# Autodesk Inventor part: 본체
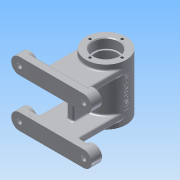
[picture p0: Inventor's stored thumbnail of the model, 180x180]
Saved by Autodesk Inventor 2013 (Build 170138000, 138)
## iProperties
Created: 2015-11
Part Number: 본체
Material: 알루미늄 6061
Document SubType Name: Modeling
Designer: Administrator
Density: 2.71 g/cm^3
Mass: 359.017 g
Surface Area: 459.644 cm^2
Volume: 132.479 cm^3
Author: Administrator
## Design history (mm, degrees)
sketch "스케치1"
  geometry: L1 (-40, 40)-(40, 40); L2 (40, 20)-(-40, 20); L3 (-40, -40)-(40, -40); L4 (40, -20)-(-40, -20); A1 r 10 centre (-40, 30) between (-40, 40) and (-40, 20); A2 r 10 centre (40, 30) between (40, 20) and (40, 40); A3 r 10 centre (-40, -30) between (-40, -20) and (-40, -40); A4 r 10 centre (40, -30) between (40, -40) and (40, -20); 1 further point
  constraints: 8 end point, 8 point on circle, 4 centre point, 3 tangent, 1 parallel
extrude "돌출1" new body sketch "스케치1" distance "d6" = 10; taper "d7" = 0 deg
sketch "스케치2"
  geometry: C1 r 10 at (-40, 30); C2 r 10 at (40, 30); A1 r 10 centre (-40, 30) between (-40, 40) and (-40, 20) reference; A2 r 10 centre (40, 30) between (40, 20) and (40, 40) reference; 1 further point
  constraints: 2 centre point, 2 coincident
  dimensions: "d8" = 20 diameter of C1; "d9" = 20 diameter of C2
extrude "돌출2" join sketch "스케치2" distance "d10" = 3; taper "d11" = 0 deg
sketch "스케치3"
  geometry: C1 r 10 at (-40, -30); C2 r 10 at (40, -30); A1 r 10 centre (40, -30) between (40, -40) and (40, -20) reference; A2 r 10 centre (-40, -30) between (-40, -20) and (-40, -40) reference; 1 further point
  constraints: 2 centre point, 2 coincident
  dimensions: "d12" = 20 diameter of C1; "d13" = 20 diameter of C2
extrude "돌출3" join sketch "스케치3" distance "d14" = 3; taper "d15" = 0 deg
sketch "스케치4"
  geometry: L1 (0, 0)-(0, 68); C1 r 25 at (0, 68)
  constraints: 2 end point, 1 centre point, 1 coincident, 1 vertical
  dimensions: "d16" = 68 distance of L1.start L1.end; "d17" = 50 diameter of C1
extrude "돌출4" join sketch "스케치4" stored distance "d18" = 70; taper "d19" = 0 deg
sketch "스케치5"
  geometry: L1 (0, 10)-(80, 10) reference; L2 (65, 68)-(65, 10); L3 (65, 10)-(15, 10); L4 (15, 10)-(15, 68); L5 (15, 68)-(65, 68); 1 further point
  constraints: 8 end point, 3 perpendicular, 2 point on line
extrude "돌출5" join sketch "스케치5" distance "d23" = 8; taper "d24" = 0 deg
sketch "스케치6"
  geometry: L1 (0, 10)-(80, 10) reference; L2 (65, 68)-(65, 10); L3 (65, 10)-(15, 10); L4 (15, 10)-(15, 68); L5 (15, 68)-(65, 68); 1 further point
  constraints: 8 end point, 3 perpendicular, 2 point on line
extrude "돌출6" join sketch "스케치6" distance "d28" = 8; taper "d29" = 0 deg
sketch "스케치7"
  geometry: L1 (0, 0)-(33, 0); L2 (33, -20)-(23, -20); L3 (23, -20)-(23, 20); L4 (23, -20)-(53, -20); L5 (53, -20)-(53, 20); L6 (53, 20)-(23, 20)
  constraints: 12 end point, 2 perpendicular, 1 horizontal, 1 parallel
extrude "돌출7" join sketch "스케치7" stored distance "d40" = 8; taper "d41" = 0 deg
hole "구멍1" diameter "d44" = 6; stored, may be unused: countersink angle "d48" = 90 deg, drill point angle "d50" = 118 deg; dims "d42" = 10, "d43" = 10, "d45" = 6, "d46" = 12, "d47" = 4, "d49" = 13
hole "구멍2" diameter "d53" = 6; stored, may be unused: countersink angle "d57" = 90 deg, drill point angle "d59" = 118 deg; dims "d51" = 10, "d52" = 10, "d54" = 6, "d55" = 12, "d56" = 4, "d58" = 13
hole "구멍3" diameter "d62" = 6; stored, may be unused: countersink angle "d66" = 90 deg, drill point angle "d68" = 118 deg; dims "d60" = 10, "d61" = 10, "d63" = 6, "d64" = 12, "d65" = 4, "d67" = 13
hole "구멍4" diameter "d71" = 6; stored, may be unused: countersink angle "d75" = 90 deg, drill point angle "d77" = 118 deg; dims "d69" = 10, "d70" = 10, "d72" = 6, "d73" = 12, "d74" = 4, "d76" = 13
chamfer "모따기1" distance "d78" = 1; stored, may be unused: second distance "d79" = 2, angle "d80" = 45 deg
chamfer "모따기2" distance "d81" = 1; stored, may be unused: second distance "d82" = 2, angle "d83" = 45 deg
chamfer "모따기3" distance "d84" = 1; stored, may be unused: second distance "d85" = 2, angle "d86" = 45 deg
chamfer "모따기4" distance "d87" = 1; stored, may be unused: second distance "d88" = 2, angle "d89" = 45 deg
node "작업 평면2"
sketch "스케치8"
  geometry: C1 r 5 at (0, 0); 1 further point
  constraints: 1 centre point, 1 coincident
  dimensions: "d91" = 10 diameter of C1
extrude "돌출8" join sketch "스케치8" stored distance "d92" = 8; taper "d93" = 0 deg
sketch "스케치9"
  geometry: C1 r 25 at (0, 0) reference; C2 r 16 at (0, 0); 1 further point
  constraints: 1 centre point, 1 coincident
  dimensions: "d94" = 32 diameter of C2
extrude "돌출9" cut sketch "스케치9" distance "d95" = 12; taper "d96" = 0 deg
sketch "스케치10"
  geometry: C1 r 16 at (0, 0) reference; C2 r 14 at (0, 0); 1 further point
  constraints: 1 centre point, 1 coincident
  dimensions: "d97" = 28 diameter of C2
extrude "돌출10" cut sketch "스케치10" distance "d98" = 2; taper "d99" = 0 deg
sketch "스케치11"
  geometry: C1 r 25 at (0, 0) reference; C2 r 16 at (0, 0); 1 further point
  constraints: 1 centre point, 1 coincident
  dimensions: "d100" = 32 diameter of C2
extrude "돌출11" cut sketch "스케치11" distance "d101" = 12; taper "d102" = 0 deg
sketch "스케치12"
  geometry: C1 r 16 at (0, 0) reference; C2 r 14 at (0, 0); 1 further point
  constraints: 1 centre point, 1 coincident
  dimensions: "d103" = 28 diameter of C2
extrude "돌출12" cut sketch "스케치12" distance "d104" = 2; taper "d105" = 0 deg
sketch "스케치13"
  geometry: C1 r 21 at (0, 0); 1 further point
  constraints: 1 centre point
  dimensions: "d106" = 42 diameter of C1
extrude "돌출13" cut sketch "스케치13" distance "d107" = 42; taper "d108" = 0 deg
hole "구멍5" diameter "d111" = 5.188; stored, may be unused: countersink angle "d115" = 90 deg, drill point angle "d117" = 0 deg; dims "d112" = 6, "d113" = 12, "d114" = 4, "d116" = 13, "d206" = 10, "d207" = 10
sketch "스케치14"
  geometry: C1 r 25 at (0, 0) reference; A1 r 20 centre (0, 0) between (0, 20) and (-20, 0); 3 further points
  constraints: 4 point on circle, 1 centre point, 1 coincident
  dimensions: "d118" = 40 diameter of A1
hole "구멍6" sketch "스케치14" at (0, 20), (-20, 0), (20, 0), (0, -20) diameter "d119" = 3.242; stored, may be unused: countersink angle "d123" = 90 deg, drill point angle "d125" = 118 deg; dims "d120" = 8, "d121" = 12, "d122" = 4, "d124" = 10
sketch "스케치15"
  geometry: C1 r 25 at (0, 0) reference; A1 r 20 centre (0, 0) between (0, 20) and (20, 0); 3 further points
  constraints: 4 point on circle, 1 centre point, 1 coincident
  dimensions: "d126" = 40 diameter of A1
hole "구멍7" sketch "스케치15" at (0, 20), (20, 0), (0, -20), (-20, 0) diameter "d127" = 3.242; stored, may be unused: countersink angle "d131" = 90 deg, drill point angle "d133" = 118 deg; dims "d128" = 8, "d129" = 12, "d130" = 4, "d132" = 10
sketch "스케치16"
  geometry: L1 (0, 0)-(0, 68); L2 (0, 68)-(14, 43.751)
  constraints: 4 end point, 1 vertical
  dimensions: "d134" = 68 distance of L1.start L1.end; "d136" = 28 distance of L1.end L2.end; "d137" = 30 deg angle of L2 L1
node "작업 평면3"
sketch "스케치18"
  geometry: L1 (8, 29.5)-(-8, 29.5); L2 (-8, 36.5)-(8, 36.5); A1 r 3.5 centre (8, 33) between (8, 29.5) and (8, 36.5); A2 r 3.5 centre (-8, 33) between (-8, 36.5) and (-8, 29.5); 1 further point
  constraints: 4 end point, 4 point on circle, 2 centre point, 2 tangent
extrude "돌출15" cut sketch "스케치18" stored distance "d157" = 42; taper "d158" = 0 deg
sketch "스케치21"
  geometry: L1 (0, 0)-(0, 68); L2 (0, 68)-(-14, 43.751)
  constraints: 4 end point, 1 vertical
  dimensions: "d173" = 68 distance of L1.start L1.end; "d176" = 28 distance of L1.end L2.end
node "작업 평면6"
sketch "스케치22"
  geometry: C1 r 6 at (0, 0); 1 further point
  constraints: 1 centre point
  dimensions: "d177" = 12 diameter of C1
extrude "돌출16" join sketch "스케치22" stored distance "d178" = 42; taper "d179" = 0 deg
hole "구멍9" diameter "d182" = 5.188; stored, may be unused: countersink angle "d186" = 90 deg, drill point angle "d188" = 0 deg; dims "d183" = 8, "d184" = 12, "d185" = 4, "d187" = 10, "d208" = 10, "d209" = 10
node "작업 평면7"
sketch "스케치23"
  geometry: L1 (68, -35)-(68, 35); L2 (93, 35)-(43, 35) reference; L3 (93, 0)-(43, 0); 2 further points
  constraints: 4 end point, 1 parallel, 1 other
  dimensions: "d191" = 35 distance between parallel lines of L2 L3
feature "엠보싱2" sketch "스케치23" dims "d192" = 0.5, "d193" = 0
fillet "모깎기3" dims "d194" = 2, "d197" = 2, "d198" = 0.3, "d199" = 3, "d210" = 0.3
chamfer "모따기5" distance "d200" = 1; stored, may be unused: second distance "d201" = 2, angle "d202" = 45 deg
chamfer "모따기6" distance "d203" = 1; stored, may be unused: second distance "d204" = 2, angle "d205" = 45 deg
node "솔리드1"
other parameters: "d90" = 96, "d189" = 25
